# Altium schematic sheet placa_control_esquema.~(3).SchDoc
size A4
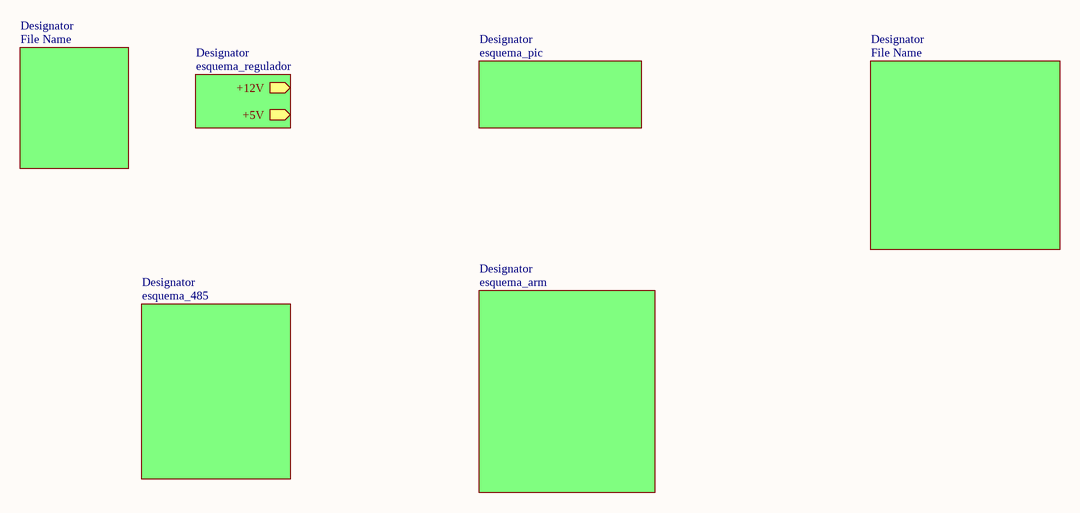
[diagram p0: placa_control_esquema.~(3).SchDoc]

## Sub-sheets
Designator = esquema_regulador: +12V (out), +5V (out)
Designator = esquema_pic: no entries
Designator = esquema_485: no entries
Designator = esquema_arm: no entries
Designator = File Name: no entries
Designator = File Name: no entries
